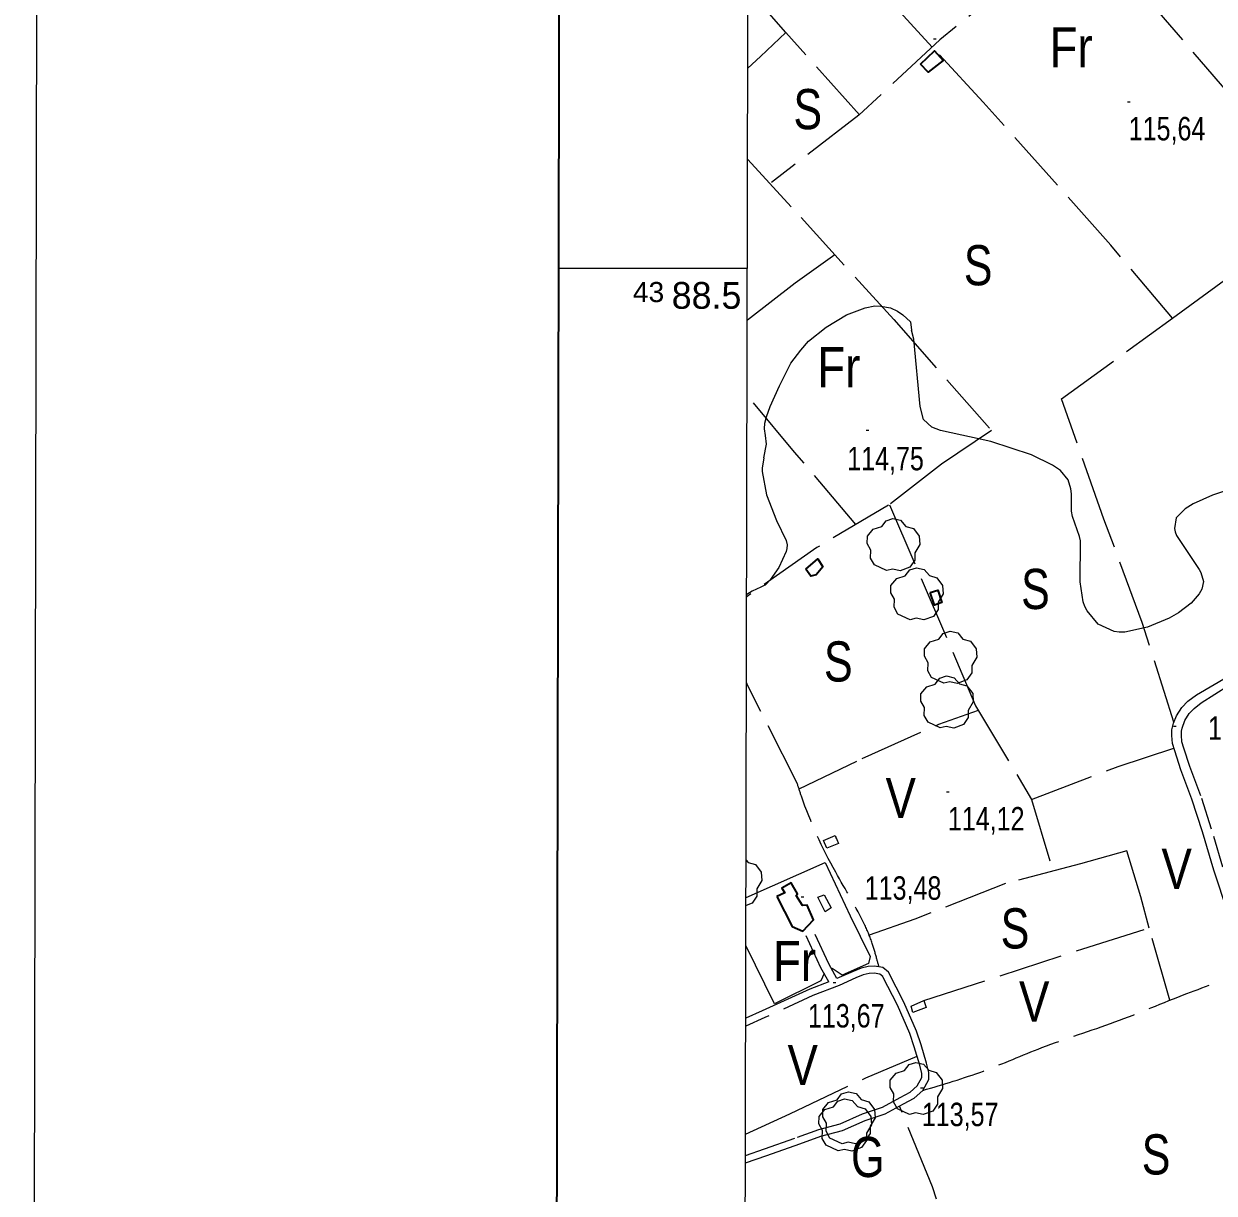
# Model space of a CAD drawing. Extents: x 483840 to 488445, y 4386047 to 4389027.
# Drawn here: x 483839.6 to 484284.3, y 4388154.7 to 4388591.4 of the extents above; entities that cross this region are included whole.
import ezdxf
from ezdxf.enums import TextEntityAlignment as Align

# ---------------------------------------------------------------- set-up
doc = ezdxf.new("R2010")
doc.units = 0
doc.header["$LTSCALE"] = 4
for name, pattern in [('DOTTED', [1.5, 0.3, -1.2]), ('LONG_DASHED', [7.5, 6, -1.5]), ('MEDIUM_DASHED', [4.5, 3, -1.5])]:
    doc.linetypes.add(name, pattern=pattern)
for name, color, linetype, lineweight in [('1', 7, 'Continuous', 13), ('2', 7, 'DOTTED', 13), ('21', 7, 'Continuous', 25), ('25', 7, 'LONG_DASHED', 25), ('29', 7, 'Continuous', 13), ('38', 7, 'Continuous', 25), ('47', 7, 'Continuous', 35), ('48', 7, 'MEDIUM_DASHED', 25), ('51', 7, 'Continuous', 13), ('7', 7, 'Continuous', 13), ('9', 7, 'Continuous', 13)]:
    doc.layers.add(name, color=color, linetype=linetype, lineweight=lineweight)
doc.layers.add('31', color=7, linetype='Continuous')

msp = doc.modelspace()

# ---------------------------------------------------------------- linework, layer by layer
at = {"layer": '1'}
msp.add_line((484109.94, 4388500), (484039.46, 4388500), dxfattribs=at)
at = {"layer": '1', "lineweight": 25}
msp.add_lwpolyline([(483845.33, 4389027.42), (488445.32, 4389018.55), (488439.58, 4386047.03), (483839.59, 4386055.9), (483845.33, 4389027.2)], dxfattribs=at)
at = {"layer": '1', "lineweight": 35}
msp.add_lwpolyline([(484040.1, 4388831.88), (487756.5, 4388824.71), (487751.76, 4386369.72), (484035.36, 4386376.89)], close=True, dxfattribs=at)
at = {"layer": '1'}
msp.add_lwpolyline([(484110.5, 4388760.3), (487685.8, 4388753.5), (487681.9, 4386441.2), (484105.5, 4386448.1)], close=True, dxfattribs=at)
at = {"layer": '21'}
msp.add_lwpolyline([(484136.26, 4388265.18), (484138.62, 4388266.07), (484141.24, 4388261.29), (484138.94, 4388259.78)], close=True, dxfattribs=at)
at = {"layer": '25'}
msp.add_line((484216.06, 4388301.76), (484224.03, 4388274.99), dxfattribs=at)
for points in [[(484268.75, 4388481.51), (484245.71, 4388508.72), (484198.03, 4388562.21), (484178.94, 4388582.77), (484155.38, 4388608.75), (484116.53, 4388653.12), (484110.28, 4388660.09)], [(484268.75, 4388481.51), (484326.4, 4388523.51), (484292.18, 4388562.7), (484258.22, 4388602.08), (484234.65, 4388628.06), (484181.86, 4388585.49), (484151.6, 4388557.27), (484118.9, 4388532.19)], [(484151.78, 4388557.44), (484124.32, 4388588.19), (484110.16, 4388604.37)], [(484110.1, 4388574.81), (484114.84, 4388579.2), (484124.32, 4388588.19)], [(484110.03, 4388540.76), (484130, 4388519.06), (484164.61, 4388480.93), (484201.16, 4388439.53), (484182.38, 4388426.9), (484162.67, 4388411.59), (484135.81, 4388395.78), (484109.81, 4388377.57), (484109.67, 4388377.45)], [(484109.9, 4388480.82), (484127.72, 4388494.72), (484142.55, 4388505.24)], [(484269.23, 4388330.64), (484257.45, 4388367.82), (484243.11, 4388406.47), (484227.25, 4388451.35), (484268.75, 4388481.51)], [(484150.45, 4388404.4), (484127.57, 4388431.44), (484109.84, 4388452.79)], [(484162.95, 4388411.81), (484195.17, 4388336.74), (484216.06, 4388301.76), (484248.38, 4388314.08), (484269.26, 4388320.92)], [(484128.5, 4388307.78), (484110.22, 4388343.97), (484109.6, 4388345.36)], [(484129.2, 4388305.69), (484152.79, 4388317.02), (484181.49, 4388329.82), (484196.21, 4388335.01)], [(484267.69, 4388226.69), (484260.07, 4388253.7), (484256.94, 4388265.37), (484251.63, 4388282.53), (484234.36, 4388277.7), (484206.32, 4388270.31), (484172.5, 4388257.01), (484155.35, 4388250.97)], [(484175.83, 4388226.59), (484235.27, 4388245.89), (484260.07, 4388253.7)], [(484109.24, 4388176.69), (484125.75, 4388184.35), (484154.16, 4388197.76), (484173.3, 4388205.83)], [(484202.33, 4388087.9), (484190.36, 4388124.07), (484179.01, 4388157), (484166.77, 4388187.21)]]:
    msp.add_lwpolyline(points, dxfattribs=at)
at = {"layer": '29'}
for points in [[(484161.91, 4388387.23), (484157.37, 4388389.35), (484155.96, 4388391.89), (484156.06, 4388394.87), (484154.69, 4388397.28), (484154.73, 4388400.03), (484156.89, 4388402.63), (484160.08, 4388403.63), (484161.73, 4388405.82), (484164.3, 4388406.65), (484167.16, 4388406), (484169.11, 4388403.73), (484171.92, 4388402.91), (484174.05, 4388400.06), (484174.29, 4388396.93), (484172.41, 4388393.78), (484172.41, 4388391.1), (484170.59, 4388388.49), (484166.97, 4388387.15), (484164.2, 4388387.78)], [(484170.72, 4388368.84), (484166.18, 4388370.96), (484164.77, 4388373.5), (484164.87, 4388376.48), (484163.5, 4388378.89), (484163.54, 4388381.64), (484165.7, 4388384.24), (484168.89, 4388385.24), (484170.54, 4388387.43), (484173.11, 4388388.26), (484175.97, 4388387.61), (484177.92, 4388385.34), (484180.73, 4388384.52), (484182.86, 4388381.67), (484183.1, 4388378.54), (484181.22, 4388375.39), (484181.22, 4388372.71), (484179.4, 4388370.1), (484175.78, 4388368.76), (484173.01, 4388369.39)], [(484183.26, 4388345.15), (484178.72, 4388347.27), (484177.31, 4388349.81), (484177.41, 4388352.79), (484176.04, 4388355.2), (484176.08, 4388357.95), (484178.24, 4388360.55), (484181.43, 4388361.55), (484183.08, 4388363.74), (484185.65, 4388364.57), (484188.51, 4388363.92), (484190.46, 4388361.65), (484193.27, 4388360.83), (484195.4, 4388357.98), (484195.64, 4388354.85), (484193.76, 4388351.7), (484193.76, 4388349.02), (484191.94, 4388346.41), (484188.32, 4388345.07), (484185.55, 4388345.7)], [(484181.94, 4388328.43), (484177.4, 4388330.55), (484175.99, 4388333.09), (484176.09, 4388336.07), (484174.72, 4388338.48), (484174.76, 4388341.23), (484176.92, 4388343.83), (484180.11, 4388344.83), (484181.76, 4388347.02), (484184.33, 4388347.85), (484187.19, 4388347.2), (484189.14, 4388344.93), (484191.95, 4388344.11), (484194.08, 4388341.26), (484194.32, 4388338.13), (484192.44, 4388334.98), (484192.44, 4388332.3), (484190.62, 4388329.69), (484187, 4388328.35), (484184.23, 4388328.98)], [(484170.48, 4388184.08), (484165.94, 4388186.2), (484164.53, 4388188.74), (484164.63, 4388191.72), (484163.26, 4388194.13), (484163.3, 4388196.88), (484165.46, 4388199.48), (484168.65, 4388200.48), (484170.3, 4388202.67), (484172.87, 4388203.5), (484175.73, 4388202.85), (484177.68, 4388200.58), (484180.49, 4388199.76), (484182.62, 4388196.91), (484182.86, 4388193.78), (484180.98, 4388190.63), (484180.98, 4388187.95), (484179.16, 4388185.34), (484175.54, 4388184), (484172.77, 4388184.63)], [(484145.28, 4388173.12), (484140.74, 4388175.24), (484139.33, 4388177.78), (484139.43, 4388180.76), (484138.06, 4388183.17), (484138.1, 4388185.92), (484140.26, 4388188.52), (484143.45, 4388189.52), (484145.1, 4388191.71), (484147.67, 4388192.54), (484150.53, 4388191.89), (484152.48, 4388189.62), (484155.29, 4388188.8), (484157.42, 4388185.95), (484157.66, 4388182.82), (484155.78, 4388179.67), (484155.78, 4388176.99), (484153.96, 4388174.38), (484150.34, 4388173.04), (484147.57, 4388173.67)], [(484143.86, 4388170.48), (484139.32, 4388172.6), (484137.91, 4388175.14), (484138.01, 4388178.12), (484136.64, 4388180.53), (484136.68, 4388183.28), (484138.84, 4388185.88), (484142.03, 4388186.88), (484143.68, 4388189.07), (484146.25, 4388189.9), (484149.11, 4388189.25), (484151.06, 4388186.98), (484153.87, 4388186.16), (484156, 4388183.31), (484156.24, 4388180.18), (484154.36, 4388177.03), (484154.36, 4388174.35), (484152.54, 4388171.74), (484148.92, 4388170.4), (484146.15, 4388171.03)]]:
    msp.add_lwpolyline(points, close=True, dxfattribs=at)
msp.add_lwpolyline([(484109.46, 4388279.05), (484110.16, 4388278.23), (484112.97, 4388277.41), (484115.1, 4388274.56), (484115.34, 4388271.43), (484113.46, 4388268.28), (484113.46, 4388265.6), (484111.64, 4388262.99), (484109.42, 4388262.17)], dxfattribs=at)
at = {"layer": '38'}
for points in [[(484322.32, 4388164.8), (484313.15, 4388191.25), (484307.52, 4388206.8), (484300.85, 4388224.52), (484296.33, 4388237.27), (484289.39, 4388259.54), (484284.16, 4388275.33), (484279.93, 4388289.61), (484276, 4388301.88), (484271.88, 4388312.8), (484269.55, 4388319.83), (484268.77, 4388322.64), (484268.53, 4388325.64), (484268.53, 4388327.74), (484269.05, 4388330.2), (484270.18, 4388332.93), (484272.19, 4388336.06), (484274.44, 4388338.39), (484277.68, 4388340.83), (484299.63, 4388353.66)], [(484140.29, 4388233.61), (484137.4, 4388238.87), (484131.82, 4388250.84)], [(484109.21, 4388165.98), (484117.2, 4388168.69), (484129.52, 4388173.11), (484137.39, 4388175.89), (484145.49, 4388178.1), (484153.89, 4388181.85), (484161.43, 4388184.34), (484168.28, 4388188.02), (484172.27, 4388190.17), (484175.45, 4388193.04), (484177.71, 4388197.13), (484177.71, 4388199.71), (484176.86, 4388203.18), (484174.79, 4388210.06), (484173.11, 4388215.22), (484168.42, 4388225.98), (484162.63, 4388237.26), (484160.47, 4388238.97), (484157.39, 4388239.51), (484154.98, 4388239.31), (484152.39, 4388238.69), (484149.43, 4388237.5), (484143.35, 4388234.81)], [(484140.29, 4388233.61), (484133.27, 4388230.88), (484115.47, 4388222.72), (484109.33, 4388220)]]:
    msp.add_lwpolyline(points, dxfattribs=at)
at = {"layer": '38', "linetype": 'MEDIUM_DASHED'}
for points in [[(484325.12, 4388165.83), (484316.48, 4388192.47), (484310.84, 4388208.03), (484304.18, 4388225.74), (484299.69, 4388238.39), (484292.76, 4388260.63), (484287.54, 4388276.39), (484283.32, 4388290.66), (484279.35, 4388303.05), (484275.22, 4388313.99), (484272.94, 4388320.87), (484272.27, 4388323.26), (484272.07, 4388325.78), (484272.07, 4388327.28), (484272.34, 4388328.29), (484273.35, 4388331.23), (484274.98, 4388333.8), (484276.85, 4388335.72), (484279.48, 4388337.82), (484297.65, 4388349.35)], [(484143.35, 4388234.81), (484140.34, 4388240.38), (484134.81, 4388252.23)], [(484109.22, 4388168.78), (484116.33, 4388171.19), (484128.63, 4388175.61), (484136.6, 4388178.42), (484144.59, 4388180.6), (484152.93, 4388184.32), (484160.38, 4388186.78), (484167.03, 4388190.35), (484170.73, 4388192.35), (484173.35, 4388194.71), (484175.06, 4388197.81), (484175.06, 4388199.39), (484174.3, 4388202.48), (484172.26, 4388209.27), (484170.63, 4388214.28), (484166.03, 4388224.84), (484160.54, 4388235.54), (484159.36, 4388236.47), (484157.27, 4388236.84), (484155.4, 4388236.69), (484153.2, 4388236.16), (484150.46, 4388235.06), (484144.16, 4388232.27), (484134.31, 4388228.44), (484116.43, 4388220.24), (484109.33, 4388217.02)]]:
    msp.add_lwpolyline(points, dxfattribs=at)
at = {"layer": '38', "linetype": 'LONG_DASHED'}
for points in [[(484159.1, 4388239.21), (484158.31, 4388242.01), (484156.58, 4388247.93), (484153.8, 4388254.76), (484142.9, 4388274.55), (484130.12, 4388302.89), (484128.5, 4388307.78)], [(484175.45, 4388193.04), (484198.09, 4388200.29), (484219.93, 4388209.04), (484247.22, 4388218.62), (484274.12, 4388229.22), (484296.33, 4388237.27)]]:
    msp.add_spline(points, degree=3, dxfattribs=at)
at = {"layer": '47'}
for points in [[(484174.54, 4388576.4), (484179.77, 4388581.28), (484183.1, 4388577.68), (484177.45, 4388573.43)], [(484131.75, 4388387.78), (484136.29, 4388391.56), (484138.04, 4388388.64), (484135.57, 4388385.64), (484133.65, 4388385.15)], [(484178.23, 4388378.99), (484181.05, 4388379.92), (484182.58, 4388375.27), (484179.76, 4388374.34)], [(484120.93, 4388265.47), (484126.61, 4388254.31), (484130.67, 4388252.53), (484134.65, 4388256.77), (484132.21, 4388262.23), (484130.56, 4388262.06), (484128.13, 4388265.86), (484128.68, 4388266.52), (484126.27, 4388270.53), (484122.84, 4388268.57), (484123.95, 4388266.89)]]:
    msp.add_lwpolyline(points, close=True, dxfattribs=at)
at = {"layer": '47', "lineweight": 13}
msp.add_lwpolyline([(484171.04, 4388224.49), (484175.83, 4388226.59), (484176.69, 4388223.97), (484171.76, 4388222.1)], close=True, dxfattribs=at)
at = {"layer": '48'}
msp.add_lwpolyline([(484138.36, 4388286.4), (484142.65, 4388288.22), (484143.89, 4388285.3), (484139.6, 4388283.48)], close=True, dxfattribs=at)
at = {"layer": '51'}
for points in [[(484109.43, 4388265.09), (484138.95, 4388278.2), (484148.36, 4388258.25), (484155.82, 4388243.01), (484155.2, 4388240.44), (484145.26, 4388236.13), (484141.55, 4388238.52)], [(484138.62, 4388236.67), (484137.31, 4388234.02), (484120.04, 4388225.41), (484109.39, 4388247.2)]]:
    msp.add_lwpolyline(points, dxfattribs=at)
at = {"layer": '7'}
for p, q in [((484179.5, 4388585.83), (484180.5, 4388585.83)), ((484251.88, 4388562.27), (484252.88, 4388562.27)), ((484154.33, 4388439.62), (484155.33, 4388439.62)), ((484269.06, 4388329.06), (484270.06, 4388329.06)), ((484184.31, 4388304.51), (484185.31, 4388304.51)), ((484130.05, 4388265.35), (484131.05, 4388265.35)), ((484141.91, 4388233.31), (484142.91, 4388233.31)), ((484174.59, 4388194.06), (484175.59, 4388194.06))]:
    msp.add_line(p, q, dxfattribs=at)
at = {"layer": '9'}
for points in [[(484116.04, 4388429.32), (484117.07, 4388434.4), (484116.67, 4388437.61), (484116.27, 4388440.21), (484116.47, 4388442.22), (484117.07, 4388444.63), (484118.47, 4388448.44), (484121.88, 4388456.26), (484126.09, 4388464.68), (484129.9, 4388469.49), (484132.71, 4388472.9), (484139.32, 4388478.12), (484146.94, 4388482.73), (484153.96, 4388485.34), (484157.57, 4388486.14), (484159.77, 4388485.94), (484163.38, 4388485.34), (484165.98, 4388484.14), (484167.99, 4388482.73), (484170.8, 4388480.12), (484171.26, 4388477.04)], [(484291.18, 4388417.81), (484283.71, 4388415.39), (484276.44, 4388412.09), (484273.5, 4388410.25), (484270.15, 4388406.91), (484269.46, 4388402.98), (484269.75, 4388401.68), (484270.26, 4388400.3), (484278.69, 4388387.65), (484279.32, 4388386.46), (484280.34, 4388383.1), (484279.67, 4388380.26), (484278.68, 4388378.5), (484275.76, 4388375.02), (484271.03, 4388371.4), (484267.46, 4388369.46), (484259.33, 4388366.07), (484250.91, 4388364.23), (484248.86, 4388364.24), (484246.93, 4388364.47), (484240.98, 4388367.17), (484236.81, 4388372.12), (484236, 4388373.78), (484235.33, 4388375.55), (484234.19, 4388382.98), (484234.42, 4388398.34), (484234.04, 4388399.98), (484231.37, 4388407.36), (484230.99, 4388409.34), (484230.97, 4388415.89), (484230.72, 4388417.72), (484229.8, 4388421.09), (484226.94, 4388424.59), (484223.96, 4388426.61), (484216.07, 4388430.39), (484200.89, 4388435.39), (484182.08, 4388439.5), (484178.83, 4388440.83), (484175.7, 4388443.62), (484174.47, 4388448.51), (484172.04, 4388473.69), (484171.26, 4388477.04)], [(484116.04, 4388429.32), (484115.43, 4388425.49), (484115.4, 4388424.23), (484117.11, 4388415.53), (484120.76, 4388405.86), (484124.36, 4388398.39), (484124.82, 4388396.86), (484124.69, 4388395.44), (484124.39, 4388394.39), (484121.64, 4388388.4), (484118.45, 4388383.76), (484116.97, 4388382.16), (484116.5, 4388381.8), (484116.14, 4388381.66), (484114.99, 4388380.96), (484111.67, 4388379.57), (484109.67, 4388378.3)], [(484143.13, 4388287.09), (484143.15, 4388287.48), (484142.88, 4388287.67)]]:
    msp.add_lwpolyline(points, dxfattribs=at)

# ---------------------------------------------------------------- texts
at = {"layer": '2', "width": 1.05}
msp.add_text('43', height=7.5, dxfattribs=at).set_placement((484078.84, 4388487.5), align=Align.RIGHT)
at = {"layer": '2'}
msp.add_text('88.5', height=10, dxfattribs=at).set_placement((484107.67, 4388485), align=Align.RIGHT)
at = {"layer": '31'}
for s, width, p in [('Fr', 0.85, (484230.85, 4388575.18)), ('S', 0.8, (484132.47, 4388552.07)), ('S', 0.8, (484196.12, 4388493.77)), ('Fr', 0.85, (484144.05, 4388455.68)), ('S', 0.8, (484217.53, 4388372.85)), ('S', 0.8, (484143.88, 4388345.77)), ('V', 0.85, (484167.21, 4388294.79)), ('V', 0.85, (484270.3, 4388268.32)), ('S', 0.8, (484209.89, 4388246.07)), ('Fr', 0.85, (484127.55, 4388233.85)), ('V', 0.85, (484217.06, 4388218.75)), ('V', 0.85, (484130.59, 4388195.05)), ('G', 0.8, (484154.88, 4388160.69)), ('S', 0.8, (484262.59, 4388161.64))]:
    msp.add_text(s, height=15, dxfattribs=dict(at, width=width)).set_placement(p, align=Align.CENTER)
at = {"layer": '7', "width": 0.8}
for s, p in [('115,64', (484252.38, 4388547.9)), ('114,75', (484147.21, 4388424.65)), ('114,29', (484281.99, 4388324.02)), ('114,12', (484184.81, 4388290.14)), ('113,48', (484153.75, 4388264.26)), ('113,67', (484132.53, 4388216.54)), ('113,57', (484175.09, 4388179.69))]:
    msp.add_text(s, height=8.75, dxfattribs=at).set_placement(p)

doc.saveas('drawing.dxf')
